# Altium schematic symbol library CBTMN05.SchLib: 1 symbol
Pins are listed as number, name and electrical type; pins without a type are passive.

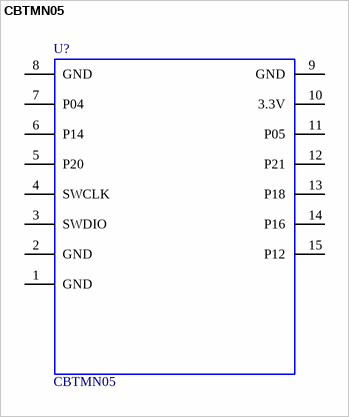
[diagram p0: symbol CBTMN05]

## CBTMN05
designator U?
module CBTMN05
footprint CBTMN05
pins: 1 GND, 2 GND, 3 SWDIO, 4 SWCLK, 5 P20, 6 P14, 7 P04, 8 GND, 9 GND, 10 3.3V, 11 P05, 12 P21, 13 P18, 14 P16, 15 P12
